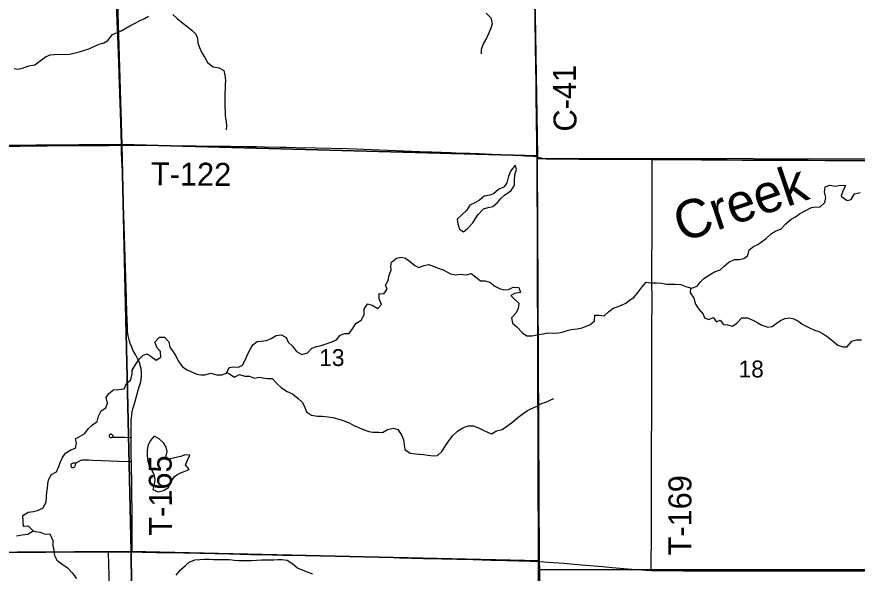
# Model space of a CAD drawing. Extents: x 0 to 34, y 0 to 22.
# Drawn here: x 6.091 to 7.13, y 16.228 to 16.916 of the extents above; entities that cross this region are included whole.
import ezdxf

# ---------------------------------------------------------------- set-up
doc = ezdxf.new("R2010")
doc.units = 0
for name, color, linetype in [('GM_X_Corporation', 7, 'Continuous'), ('GM_X_County_Road', 7, 'Continuous'), ('GM_X_County_Road_Text', 7, 'Continuous'), ('GM_X_Minor_Lake', 7, 'Continuous'), ('GM_X_Minor_River', 7, 'Continuous'), ('GM_X_Minor_River_Text', 7, 'Continuous'), ('GM_X_Section_Text', 7, 'Continuous'), ('GM_X_State_Route', 7, 'Continuous'), ('GM_X_Township_Road', 7, 'Continuous'), ('GM_X_Township_Road_Text', 7, 'Continuous')]:
    doc.layers.add(name, color=color, linetype=linetype)

msp = doc.modelspace()

# ---------------------------------------------------------------- linework, layer by layer
at = {"layer": 'GM_X_Corporation'}
for points in [[(5.736, 17.2591), (6.2055, 17.2589), (6.2208, 16.758), (5.7408, 16.7543)], [(6.2055, 17.2589), (6.7265, 17.2458), (6.7267, 17.2428), (6.7351, 16.7438), (6.2208, 16.758)], [(6.7267, 17.2428), (7.2695, 17.2343), (7.2694, 16.7399), (6.7345, 16.7408), (6.7351, 16.7438)], [(5.7408, 16.7543), (6.2208, 16.758), (6.2324, 16.2547), (5.7406, 16.2518)], [(6.2208, 16.758), (6.7351, 16.7438), (6.7345, 16.7408), (6.7371, 16.2431), (6.2324, 16.2547)], [(6.7345, 16.7408), (7.2694, 16.7399), (7.2607, 16.2324), (6.7375, 16.2321), (6.7371, 16.2431)], [(6.2324, 16.2547), (6.2375, 15.7484), (5.7409, 15.7462), (5.7406, 16.2518)], [(6.2324, 16.2547), (6.7371, 16.2431), (6.7375, 16.2321), (6.7392, 15.7414), (6.2375, 15.7484)], [(6.7375, 16.2321), (7.2607, 16.2324), (7.2545, 15.7306), (6.7388, 15.7313), (6.7392, 15.7414)]]:
    msp.add_lwpolyline(points, close=True, dxfattribs=at)
msp.add_lwpolyline([(6.7318, 16.935), (6.7318, 16.9126), (6.7325, 16.8803), (6.7329, 16.8551), (6.7331, 16.8349), (6.7334, 16.8128), (6.7336, 16.7943), (6.7339, 16.756), (6.734, 16.7429), (6.7359, 16.2426), (6.7385, 15.7355)], dxfattribs=at)
msp.add_lwpolyline([(6.7318, 16.935), (6.7318, 16.9126), (6.7325, 16.8803), (6.7329, 16.8551), (6.7331, 16.8349), (6.7334, 16.8128), (6.7336, 16.7943), (6.7339, 16.756), (6.734, 16.7429), (6.7359, 16.2426), (6.7385, 15.7355)], dxfattribs=at)
at = {"layer": 'GM_X_County_Road'}
for points in [[(6.7341, 16.7426), (6.734, 16.7558), (6.7338, 16.794), (6.7335, 16.8125), (6.7332, 16.8346), (6.733, 16.8548), (6.7327, 16.88), (6.732, 16.9123), (6.7319, 16.9347), (6.7315, 16.962), (6.7314, 16.9732), (6.7311, 16.9916), (6.7305, 17.0274), (6.7293, 17.0904), (6.729, 17.1078), (6.7287, 17.118), (6.7282, 17.1392), (6.7278, 17.1595), (6.7274, 17.179), (6.7265, 17.2305), (6.7265, 17.2417)], [(6.2059, 16.1939), (6.2047, 16.2396), (6.2044, 16.2519), (6.2044, 16.2542)]]:
    msp.add_lwpolyline(points, dxfattribs=at)
at = {"layer": 'GM_X_Minor_Lake'}
for points in [[(6.6729, 16.6797), (6.6741, 16.68), (6.6798, 16.6813), (6.6855, 16.6862), (6.6895, 16.6913), (6.6943, 16.6951), (6.7023, 16.7009), (6.7065, 16.7077), (6.7065, 16.714), (6.7069, 16.7206), (6.709, 16.727), (6.7075, 16.7323), (6.7018, 16.725), (6.6989, 16.7172), (6.6972, 16.7106), (6.6936, 16.7057), (6.6868, 16.7021), (6.6807, 16.6968), (6.6759, 16.6954), (6.6689, 16.6939), (6.6632, 16.689), (6.6573, 16.6856), (6.6511, 16.683), (6.6471, 16.6762), (6.6357, 16.6658)], [(6.6357, 16.6658), (6.6366, 16.6597), (6.6384, 16.6533), (6.6435, 16.65), (6.6485, 16.6542), (6.6549, 16.6611), (6.6582, 16.6663), (6.6618, 16.6715), (6.6683, 16.6783), (6.6729, 16.6797)], [(6.2609, 16.3973), (6.2559, 16.3916), (6.2531, 16.3852), (6.2521, 16.3795), (6.252, 16.3735), (6.2531, 16.3664), (6.2548, 16.3611), (6.2574, 16.3562), (6.2602, 16.3501), (6.2615, 16.3438), (6.2607, 16.3381), (6.2592, 16.3315), (6.2656, 16.3286), (6.2722, 16.3303), (6.2785, 16.3337), (6.281, 16.3401), (6.2858, 16.3473), (6.289, 16.3493)], [(6.289, 16.3493), (6.2926, 16.3516), (6.2981, 16.3537), (6.3043, 16.3559), (6.2996, 16.362), (6.3023, 16.3686), (6.305, 16.3737), (6.2988, 16.3741), (6.294, 16.3721), (6.2882, 16.371), (6.2825, 16.3695), (6.2766, 16.368), (6.2755, 16.3731), (6.2769, 16.3784), (6.2756, 16.3836), (6.2726, 16.3885), (6.2669, 16.394), (6.2609, 16.3973)]]:
    msp.add_lwpolyline(points, dxfattribs=at)
at = {"layer": 'GM_X_Minor_River'}
for points in [[(6.0876, 16.8519), (6.0927, 16.8511), (6.098, 16.8524), (6.1058, 16.855), (6.113, 16.8565), (6.12, 16.8612), (6.1266, 16.8664), (6.1321, 16.8687), (6.1374, 16.8694), (6.1433, 16.8696), (6.1507, 16.8691), (6.1566, 16.8697), (6.163, 16.8713), (6.1698, 16.8728), (6.1747, 16.8745), (6.1799, 16.8762), (6.1854, 16.8786), (6.1926, 16.8818), (6.1986, 16.8837), (6.2034, 16.8867), (6.2091, 16.894), (6.2155, 16.8963), (6.2207, 16.8989), (6.2256, 16.9019), (6.2307, 16.9047), (6.2358, 16.9072), (6.2436, 16.9113), (6.2487, 16.9139), (6.2537, 16.9164)], [(6.2841, 16.9185), (6.2892, 16.9139), (6.2962, 16.908), (6.3011, 16.9041), (6.3077, 16.899), (6.3122, 16.8942), (6.3146, 16.8895), (6.315, 16.8834), (6.3168, 16.8779), (6.3196, 16.8714), (6.3236, 16.8653), (6.3267, 16.8592), (6.3337, 16.8541), (6.3413, 16.8527), (6.3471, 16.8493), (6.3482, 16.8436), (6.3489, 16.8371), (6.3485, 16.8318), (6.3484, 16.8165), (6.3482, 16.8111), (6.3484, 16.8041), (6.3487, 16.7983), (6.3487, 16.7933), (6.3498, 16.7859), (6.3501, 16.781), (6.3499, 16.7762)], [(6.6716, 16.9201), (6.6774, 16.9147), (6.6789, 16.907), (6.6771, 16.9017), (6.6743, 16.8947), (6.6721, 16.8892), (6.6677, 16.8822), (6.6654, 16.8752), (6.6652, 16.8701)], [(7.0651, 16.6754), (7.0739, 16.6802), (7.079, 16.681), (7.0844, 16.6806), (7.0905, 16.6862), (7.0915, 16.6923), (7.0899, 16.6989), (7.091, 16.7054), (7.0967, 16.7076), (7.1035, 16.7064), (7.11, 16.7077), (7.1162, 16.7073), (7.1129, 16.7003), (7.1106, 16.6939), (7.118, 16.6887), (7.1229, 16.6898), (7.1271, 16.6968), (7.1341, 16.6987)], [(6.6698, 16.5892), (6.6759, 16.5878), (6.6821, 16.5827), (6.6879, 16.5798), (6.6934, 16.5781), (6.6991, 16.5786), (6.705, 16.5816), (6.7118, 16.581), (6.7138, 16.5749), (6.7066, 16.5736), (6.7019, 16.5714), (6.7064, 16.5666), (6.712, 16.5617), (6.7111, 16.5548), (6.7084, 16.5493), (6.703, 16.5437), (6.704, 16.5372), (6.7094, 16.5323), (6.7166, 16.5252), (6.722, 16.5212), (6.7285, 16.5214), (6.736, 16.523), (6.7421, 16.5239), (6.7476, 16.5252), (6.7565, 16.5246), (6.7614, 16.525), (6.7667, 16.5265), (6.7718, 16.5278), (6.7767, 16.5291), (6.7841, 16.53), (6.7904, 16.5314), (6.7951, 16.5331), (6.7998, 16.535), (6.8054, 16.5401), (6.8058, 16.5467), (6.8111, 16.5469), (6.8175, 16.5461), (6.8228, 16.5512), (6.8285, 16.5557), (6.8335, 16.5574), (6.839, 16.5591), (6.8441, 16.5619), (6.849, 16.5654), (6.8541, 16.5688), (6.8595, 16.5752), (6.8646, 16.5819), (6.8694, 16.5875), (6.8752, 16.5869), (6.8822, 16.5869), (6.8887, 16.5866), (6.894, 16.5853), (6.9053, 16.5852), (6.9123, 16.585), (6.9187, 16.5825), (6.9255, 16.5802), (6.9327, 16.5828), (6.9362, 16.5879), (6.9409, 16.5924), (6.9476, 16.5966), (6.9538, 16.6005), (6.9608, 16.6029), (6.9658, 16.6073), (6.9715, 16.6124), (6.9789, 16.6157), (6.9849, 16.6157), (6.9902, 16.6168), (6.9954, 16.6206), (6.9969, 16.6276), (7.0023, 16.6317), (7.0076, 16.6342), (7.0123, 16.6375), (7.0178, 16.6419), (7.0245, 16.6477), (7.0294, 16.6507), (7.0364, 16.6535), (7.0423, 16.6597), (7.049, 16.6654), (7.0543, 16.6686), (7.059, 16.672), (7.0651, 16.6754)], [(6.2048, 16.45), (6.2105, 16.4547), (6.2173, 16.455), (6.2236, 16.4559), (6.2265, 16.4623), (6.2318, 16.4669), (6.2337, 16.4743), (6.2335, 16.479), (6.2381, 16.4862), (6.2423, 16.4924), (6.2471, 16.4975), (6.252, 16.4992), (6.2569, 16.4957), (6.2633, 16.4912), (6.269, 16.4949), (6.2687, 16.5019), (6.2644, 16.5067), (6.2616, 16.5137), (6.2673, 16.5196), (6.2737, 16.5197), (6.2788, 16.5138), (6.2804, 16.5074), (6.2842, 16.5015), (6.2877, 16.4965), (6.2907, 16.4904), (6.2958, 16.4832), (6.3018, 16.4792), (6.3137, 16.4738), (6.3186, 16.473), (6.3236, 16.4732), (6.3311, 16.4752), (6.3379, 16.4733), (6.3446, 16.4733), (6.3504, 16.4753), (6.3535, 16.4823), (6.3584, 16.483), (6.3652, 16.4828), (6.37, 16.4849), (6.3736, 16.4922), (6.3767, 16.4991), (6.3799, 16.5053), (6.3828, 16.5104), (6.3881, 16.5145), (6.3932, 16.5147), (6.3998, 16.5156), (6.4055, 16.518), (6.4116, 16.5216), (6.4182, 16.5227), (6.4241, 16.5193), (6.4265, 16.5136), (6.4318, 16.5084), (6.4368, 16.5021), (6.4433, 16.4981), (6.4506, 16.5005), (6.456, 16.506), (6.4618, 16.5083), (6.4673, 16.5092), (6.4736, 16.5114), (6.4808, 16.514), (6.4865, 16.5166), (6.4909, 16.5223), (6.4966, 16.5242), (6.5022, 16.5243), (6.5062, 16.5302), (6.5101, 16.5364), (6.5169, 16.5409), (6.5207, 16.5474), (6.5206, 16.5544), (6.5248, 16.5608), (6.5306, 16.5594), (6.5374, 16.555), (6.542, 16.5601), (6.539, 16.5672), (6.5392, 16.5736), (6.5449, 16.5732), (6.5489, 16.5791), (6.547, 16.5838), (6.5501, 16.5897), (6.5516, 16.5965), (6.554, 16.6027), (6.5534, 16.6075), (6.5544, 16.6124), (6.5607, 16.6173), (6.5663, 16.6186), (6.5718, 16.6174), (6.5782, 16.6123), (6.5831, 16.6085), (6.5882, 16.6058), (6.5948, 16.6084), (6.6, 16.6097), (6.6052, 16.6078), (6.6109, 16.6055), (6.6185, 16.6028), (6.6273, 16.598), (6.6334, 16.5968), (6.6396, 16.5977), (6.6466, 16.5967), (6.6529, 16.5984), (6.6583, 16.5944), (6.6643, 16.5892), (6.6698, 16.5892)], [(6.9243, 16.5806), (6.924, 16.5745), (6.9285, 16.568), (6.9305, 16.5604), (6.9346, 16.5543), (6.9401, 16.5482), (6.9414, 16.5435), (6.9471, 16.5416), (6.9522, 16.544), (6.9563, 16.5387), (6.9611, 16.5407), (6.965, 16.5352), (6.9699, 16.5348), (6.9761, 16.5334), (6.9815, 16.5372), (6.9879, 16.5434), (6.9949, 16.5434), (7.0012, 16.5407), (7.0074, 16.5376), (7.0127, 16.5346), (7.02, 16.5321), (7.0255, 16.5328), (7.0303, 16.5364), (7.0354, 16.5403), (7.0411, 16.5428), (7.0473, 16.5437), (7.0522, 16.5425), (7.0577, 16.5396), (7.0626, 16.5358), (7.0705, 16.5318), (7.0777, 16.5283), (7.083, 16.5266), (7.0885, 16.5239), (7.0945, 16.5199), (7.1014, 16.5138), (7.1067, 16.51), (7.1131, 16.5077), (7.1181, 16.5076), (7.124, 16.5146), (7.1295, 16.5165), (7.1359, 16.5164)], [(6.3509, 16.4765), (6.3544, 16.4738), (6.3602, 16.4703), (6.3663, 16.4735), (6.3729, 16.4714), (6.3788, 16.4714), (6.3848, 16.4692), (6.3909, 16.4702), (6.3958, 16.4694), (6.4009, 16.4684), (6.4066, 16.4687), (6.4122, 16.4628), (6.4182, 16.4571), (6.4252, 16.4525), (6.4318, 16.4498), (6.4386, 16.4443), (6.4444, 16.4388), (6.4474, 16.4327), (6.4493, 16.4274), (6.4555, 16.4231), (6.4627, 16.4222), (6.4685, 16.4219), (6.4755, 16.4211), (6.4821, 16.4202), (6.4882, 16.4186), (6.4948, 16.4167), (6.502, 16.4138), (6.508, 16.4103), (6.5156, 16.4071), (6.5206, 16.405), (6.5265, 16.403), (6.5314, 16.4024), (6.5382, 16.4024), (6.5433, 16.402), (6.5496, 16.4054), (6.5568, 16.407), (6.5621, 16.4055), (6.5673, 16.3982), (6.5694, 16.3927), (6.5699, 16.3861), (6.5708, 16.3808), (6.5776, 16.3764), (6.5842, 16.3756), (6.5941, 16.3748), (6.5995, 16.3736), (6.6062, 16.373), (6.6111, 16.3734), (6.6166, 16.3783), (6.6212, 16.3852), (6.6246, 16.3903), (6.6298, 16.3979), (6.6362, 16.4034), (6.6427, 16.4075), (6.6493, 16.4099), (6.6557, 16.4101), (6.6612, 16.4082), (6.6676, 16.4049), (6.6731, 16.4024), (6.678, 16.4001), (6.6843, 16.4037), (6.6913, 16.4057), (6.6983, 16.4104), (6.7046, 16.4149), (6.7107, 16.4202), (6.7173, 16.4253), (6.7226, 16.429), (6.7276, 16.4317), (6.7332, 16.4341), (6.7399, 16.4375), (6.7452, 16.4395), (6.7507, 16.4416), (6.7554, 16.444)], [(6.0905, 16.2741), (6.0975, 16.2755), (6.1045, 16.2761), (6.111, 16.2804), (6.1053, 16.2861), (6.0991, 16.2858), (6.0989, 16.2924), (6.0984, 16.2992), (6.1048, 16.3032), (6.1115, 16.3041), (6.1164, 16.3054), (6.1232, 16.3082), (6.1272, 16.3156), (6.1275, 16.3228), (6.1279, 16.3279), (6.1289, 16.333), (6.1294, 16.3379), (6.1302, 16.3432), (6.1337, 16.3499), (6.1398, 16.3534), (6.143, 16.3598), (6.1451, 16.3657), (6.1474, 16.371), (6.151, 16.3761), (6.1577, 16.3806), (6.1636, 16.3825), (6.1649, 16.3891), (6.1636, 16.3941), (6.1691, 16.3972), (6.175, 16.4004), (6.1794, 16.4067), (6.1844, 16.4112), (6.1902, 16.4153), (6.192, 16.422), (6.1954, 16.4288), (6.2009, 16.4325), (6.2029, 16.4382), (6.2014, 16.445), (6.2048, 16.45)], [(6.111, 16.2804), (6.1136, 16.2796), (6.1196, 16.2786), (6.1259, 16.2763), (6.1319, 16.2765), (6.1355, 16.2681)], [(6.1355, 16.2681), (6.1353, 16.2621), (6.1368, 16.256), (6.1377, 16.2499), (6.1405, 16.244), (6.1468, 16.2393), (6.1536, 16.2343), (6.1593, 16.2282), (6.1646, 16.2214)], [(6.2881, 16.2256), (6.2933, 16.2322), (6.2996, 16.2375), (6.3043, 16.2413), (6.311, 16.2443), (6.3172, 16.245), (6.3233, 16.2454), (6.329, 16.2453), (6.3343, 16.2449), (6.341, 16.2447), (6.3484, 16.2447), (6.3535, 16.245), (6.3598, 16.2439), (6.3651, 16.2435), (6.3765, 16.2434), (6.3814, 16.2436), (6.3873, 16.2439), (6.3941, 16.2443), (6.399, 16.2445), (6.404, 16.2443), (6.4087, 16.2442), (6.4139, 16.2446), (6.4186, 16.2448), (6.4254, 16.244), (6.4324, 16.2396), (6.4385, 16.2341), (6.4459, 16.231), (6.4508, 16.2293), (6.4567, 16.227)]]:
    msp.add_lwpolyline(points, dxfattribs=at)
at = {"layer": 'GM_X_State_Route'}
msp.add_lwpolyline([(6.067, 16.2539), (6.0928, 16.2539), (6.1093, 16.2539), (6.1267, 16.254), (6.1516, 16.2541), (6.1684, 16.254), (6.182, 16.2541), (6.1951, 16.2542), (6.2044, 16.2542), (6.2144, 16.2542), (6.2255, 16.2542), (6.2327, 16.2541), (6.2338, 16.2541), (6.2461, 16.2539), (6.2638, 16.2536), (6.2973, 16.2529), (6.3172, 16.2525), (6.3545, 16.2517), (6.38, 16.2511), (6.4064, 16.2506), (6.4201, 16.2503), (6.4303, 16.2501), (6.4477, 16.2498), (6.4676, 16.2494), (6.4869, 16.2488), (6.526, 16.248), (6.5468, 16.2475), (6.5636, 16.2471), (6.5642, 16.247), (6.5941, 16.2462), (6.6167, 16.2456), (6.6354, 16.2451), (6.6556, 16.2446), (6.6776, 16.244), (6.6966, 16.2435), (6.7258, 16.2427), (6.7361, 16.2423), (6.737, 16.2423), (6.7485, 16.2416), (6.7674, 16.2402), (6.7844, 16.2388), (6.7996, 16.2374), (6.8154, 16.236), (6.8277, 16.2349), (6.8463, 16.2333), (6.8639, 16.2319), (6.8695, 16.2315), (6.8757, 16.2312), (6.8854, 16.231), (6.9149, 16.2307), (6.9494, 16.2307), (6.9755, 16.2306), (7.005, 16.2306), (7.0277, 16.2306), (7.0529, 16.2308), (7.0719, 16.2307), (7.102, 16.2307), (7.1427, 16.2308)], dxfattribs=at)
at = {"layer": 'GM_X_Township_Road'}
for points in [[(6.2203, 16.757), (6.22, 16.771), (6.2192, 16.7981), (6.2179, 16.8322), (6.217, 16.8593), (6.2162, 16.8816), (6.2151, 16.9099), (6.2144, 16.9332)], [(6.0719, 16.7556), (6.0952, 16.7559), (6.1092, 16.7562), (6.1154, 16.7563), (6.1182, 16.7563), (6.1284, 16.7564), (6.1393, 16.7565), (6.1545, 16.7566), (6.1632, 16.7567), (6.1769, 16.7566), (6.1834, 16.7567), (6.1934, 16.7567), (6.1977, 16.7568), (6.2052, 16.7568), (6.2203, 16.757)], [(6.2203, 16.757), (6.2213, 16.7571), (6.2353, 16.7571), (6.2468, 16.7571), (6.253, 16.757), (6.262, 16.7569), (6.2698, 16.7567), (6.2804, 16.7565), (6.2928, 16.7563), (6.2987, 16.7562), (6.3127, 16.7561), (6.323, 16.756), (6.3478, 16.7558), (6.355, 16.7557), (6.3745, 16.7555), (6.3876, 16.7553), (6.3972, 16.7551), (6.4168, 16.7548), (6.4246, 16.7546), (6.4364, 16.7544), (6.4609, 16.7539), (6.4799, 16.7534), (6.4995, 16.7528), (6.5206, 16.752), (6.5498, 16.7509), (6.5895, 16.7494), (6.6044, 16.7488), (6.6277, 16.7479), (6.6411, 16.7474), (6.6513, 16.7471), (6.6619, 16.7466), (6.6864, 16.7455), (6.6945, 16.7453), (6.7035, 16.745), (6.7106, 16.7447), (6.7199, 16.7441), (6.7298, 16.7433), (6.7326, 16.7429), (6.7341, 16.7426)], [(6.2323, 16.3958), (6.2323, 16.4027), (6.2324, 16.4091), (6.2325, 16.4146), (6.2325, 16.4175), (6.2327, 16.4205), (6.233, 16.4225), (6.2332, 16.4242), (6.2334, 16.4258), (6.2338, 16.4276), (6.2342, 16.4294), (6.2346, 16.4312), (6.2353, 16.4335), (6.2359, 16.4357), (6.2364, 16.4375), (6.2389, 16.4462), (6.2411, 16.4542), (6.2428, 16.4596), (6.2435, 16.462), (6.2442, 16.4649), (6.2446, 16.4668), (6.2449, 16.4689), (6.2451, 16.4703), (6.2452, 16.4719), (6.2452, 16.4737), (6.2452, 16.4756), (6.2451, 16.4774), (6.2448, 16.4792), (6.2446, 16.4809), (6.2441, 16.4832), (6.2429, 16.4873), (6.2417, 16.4905), (6.2404, 16.4933), (6.2376, 16.4984), (6.235, 16.503), (6.233, 16.5073), (6.2312, 16.5119), (6.2298, 16.5164), (6.2287, 16.5213), (6.228, 16.5266), (6.2277, 16.5319), (6.2271, 16.5508), (6.2263, 16.5816), (6.2255, 16.6045), (6.2246, 16.6319), (6.2237, 16.6583), (6.2228, 16.6828), (6.2215, 16.7244), (6.2204, 16.7471), (6.2203, 16.757)], [(6.7341, 16.7426), (6.7366, 16.742), (6.7395, 16.7413), (6.743, 16.7407), (6.7456, 16.7404), (6.7476, 16.7403), (6.7513, 16.7401), (6.7557, 16.7401), (6.7865, 16.7399), (6.8123, 16.7398), (6.8362, 16.7397), (6.8635, 16.7396), (6.8767, 16.7395)], [(6.8757, 16.2312), (6.8758, 16.2457), (6.8759, 16.2663), (6.8759, 16.2822), (6.876, 16.3011), (6.876, 16.317), (6.8761, 16.3318), (6.8762, 16.3511), (6.8761, 16.3751), (6.8762, 16.3946), (6.8763, 16.4131), (6.8764, 16.4308), (6.8765, 16.4451), (6.8765, 16.4684), (6.8766, 16.4841), (6.8764, 16.5142), (6.8766, 16.5314), (6.8767, 16.5643), (6.8764, 16.5893), (6.8766, 16.613), (6.8768, 16.643), (6.8769, 16.6702), (6.8769, 16.6972), (6.877, 16.7127), (6.8768, 16.728), (6.8767, 16.7381), (6.8767, 16.7395)], [(6.8767, 16.7395), (6.8869, 16.7394), (6.9099, 16.7392), (6.9378, 16.739), (6.9698, 16.7388), (6.9888, 16.7387), (7.0124, 16.7386), (7.0401, 16.7386), (7.0547, 16.7385), (7.0699, 16.7384), (7.091, 16.7383), (7.1063, 16.7382), (7.1221, 16.7381), (7.1414, 16.7381), (7.1712, 16.7381), (7.1948, 16.7379), (7.2107, 16.7379), (7.2374, 16.7378), (7.2548, 16.7378), (7.2694, 16.7377), (7.27, 16.7377)], [(6.2104, 16.3966), (6.2102, 16.3971), (6.2099, 16.3975), (6.2096, 16.398), (6.2092, 16.3985), (6.2089, 16.3989), (6.2086, 16.3992), (6.2083, 16.3994), (6.2079, 16.3996), (6.2074, 16.3997), (6.207, 16.3998), (6.2066, 16.3997), (6.2062, 16.3995), (6.2059, 16.3994), (6.2054, 16.3988), (6.2052, 16.3984), (6.2052, 16.3981), (6.2051, 16.3977), (6.2052, 16.3972), (6.2054, 16.3966), (6.2056, 16.3962), (6.206, 16.396), (6.2065, 16.3958), (6.207, 16.3957), (6.2075, 16.3957), (6.2081, 16.3958), (6.2086, 16.396), (6.2093, 16.3961), (6.21, 16.3962), (6.2113, 16.3962), (6.216, 16.3961), (6.2237, 16.3959), (6.2323, 16.3958)], [(6.2326, 16.3658), (6.2325, 16.3708), (6.2324, 16.386), (6.2323, 16.3958)], [(6.1638, 16.364), (6.1635, 16.364), (6.1629, 16.3641), (6.1623, 16.3641), (6.1618, 16.3641), (6.1612, 16.364), (6.1605, 16.3639), (6.1599, 16.3637), (6.1594, 16.3635), (6.1589, 16.3632), (6.1586, 16.363), (6.1583, 16.3626), (6.158, 16.3623), (6.1578, 16.3618), (6.1577, 16.3614), (6.1577, 16.3609), (6.1577, 16.3605), (6.1578, 16.3601), (6.1579, 16.3596), (6.1581, 16.3593), (6.1584, 16.3589), (6.1587, 16.3587), (6.1592, 16.3585), (6.1596, 16.3584), (6.1602, 16.3584), (6.1607, 16.3585), (6.1611, 16.3586), (6.1615, 16.3588), (6.1619, 16.3591), (6.1623, 16.3595), (6.1627, 16.3601), (6.1631, 16.3606), (6.1634, 16.3613), (6.1636, 16.3618), (6.1637, 16.3624), (6.1638, 16.3629), (6.1639, 16.3635), (6.164, 16.3639), (6.1643, 16.3642), (6.1649, 16.3646), (6.1654, 16.365), (6.166, 16.3653), (6.1666, 16.3657), (6.1672, 16.366), (6.1688, 16.3668), (6.1694, 16.3672), (6.1705, 16.3675), (6.1715, 16.3678), (6.1724, 16.368), (6.1732, 16.3681), (6.1742, 16.3681), (6.1752, 16.3681), (6.1767, 16.368), (6.1801, 16.3679), (6.1848, 16.3677), (6.197, 16.3672), (6.2168, 16.3663), (6.2311, 16.3658), (6.2326, 16.3658)], [(6.2338, 16.2541), (6.2338, 16.2565), (6.2336, 16.2708), (6.2334, 16.2954), (6.233, 16.3337), (6.2326, 16.3658)]]:
    msp.add_lwpolyline(points, dxfattribs=at)

# ---------------------------------------------------------------- texts
at = {"layer": 'GM_X_County_Road_Text'}
msp.add_text('C-41', height=0.02841, rotation=90.6866, dxfattribs=at).set_placement((6.7834, 16.7741))
at = {"layer": 'GM_X_Minor_River_Text'}
msp.add_text('Creek', height=0.04737, rotation=18.6426, dxfattribs=at).set_placement((6.9132, 16.6367))
at = {"layer": 'GM_X_Section_Text'}
for s, p in [('13', (6.4651, 16.484)), ('18', (6.9838, 16.4699))]:
    msp.add_text(s, height=0.02093, rotation=0, dxfattribs=at).set_placement(p)
at = {"layer": 'GM_X_Township_Road_Text'}
for s, rotation, p in [('T-122', 359.4454, (6.2567, 16.7076)), ('T-165', 90.2779, (6.2829, 16.2743)), ('T-169', 90, (6.9254, 16.2498))]:
    msp.add_text(s, height=0.02841, rotation=rotation, dxfattribs=at).set_placement(p)

doc.saveas('drawing.dxf')
